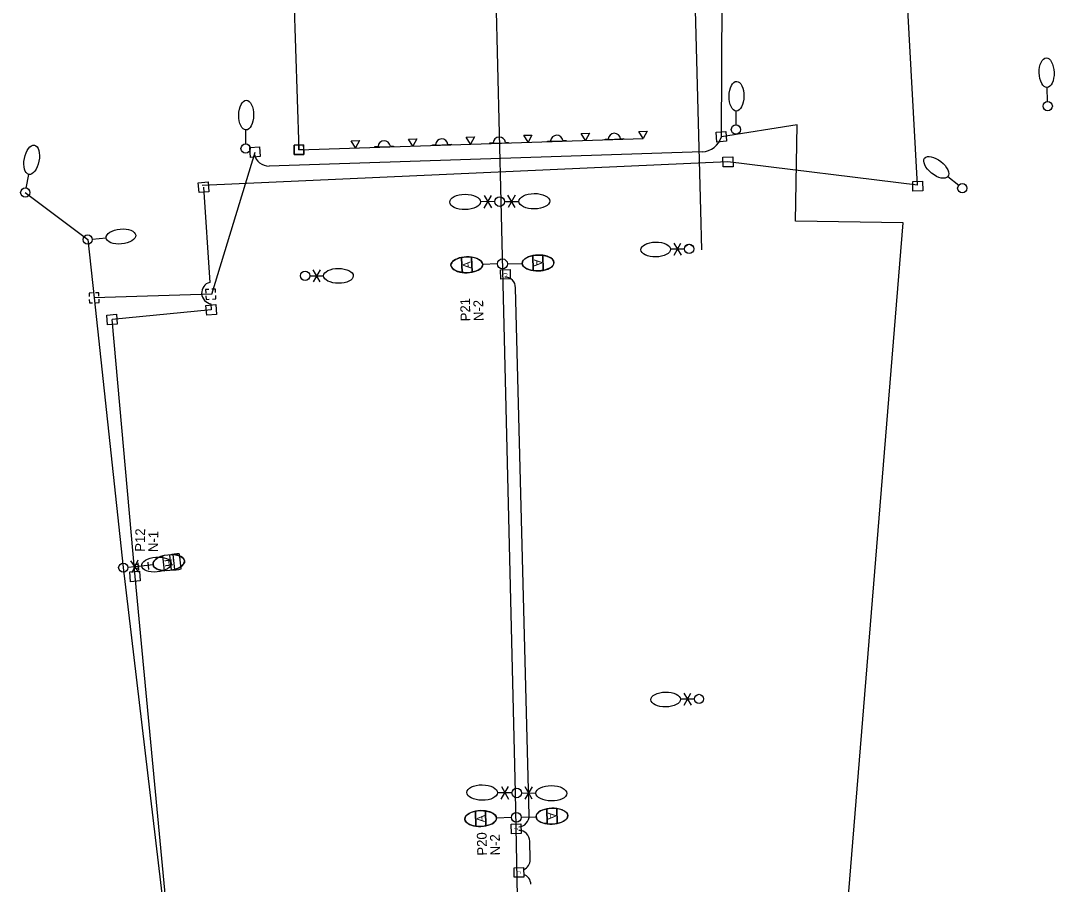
# Model space of a CAD drawing. Extents: x 925407 to 930994, y 604905 to 637063.
# Drawn here: x 929578 to 930105, y 610061 to 610502 of the extents above; entities that cross this region are included whole.
import ezdxf

# ---------------------------------------------------------------- set-up
doc = ezdxf.new("R2010")
doc.units = 0
for name, color, linetype in [('ActivePointCell_dp', 7, 'Continuous'), ('Conduit', 7, 'Continuous'), ('ConduitDB', 7, 'Continuous'), ('ConduitJB', 7, 'Continuous'), ('ConduitOT', 7, 'Continuous'), ('GPKDrCellIns_dp', 7, 'Continuous'), ('LightingMisc', 7, 'Continuous'), ('LiteCond_ep', 7, 'Continuous'), ('Miscellaneous2', 7, 'Continuous'), ('Miscellaneous9', 7, 'Continuous'), ('PoleLight', 7, 'Continuous'), ('PoleLight_ep', 7, 'Continuous'), ('PullBox', 7, 'Continuous')]:
    doc.layers.add(name, color=color, linetype=linetype)

msp = doc.modelspace()

# ---------------------------------------------------------------- linework, layer by layer
at = {"layer": 'ActivePointCell_dp'}
for p, q in [((929638.26, 610221.47), (929637.95, 610225.23)), ((929643.24, 610221.88), (929642.93, 610225.65))]:
    msp.add_line(p, q, dxfattribs=at)
at = {"layer": 'Conduit'}
for p, q in [((929822.99, 610409.48), (929815.93, 610700.2)), ((929935.24, 610442.43), (929936.2, 610609.56)), ((929973.9, 610448.58), (929935.24, 610442.43)), ((929973.1, 610399.48), (929973.9, 610448.58)), ((929675.41, 610362.13), (929697.45, 610434.6)), ((929580.32, 610414), (929612.12, 610390.03)), ((930027.95, 610398.52), (929973.1, 610399.48)), ((929999.47, 610048.38), (930027.95, 610398.52)), ((929612.12, 610390.03), (929615.35, 610360.32)), ((929675.41, 610362.13), (929615.35, 610360.32))]:
    msp.add_line(p, q, dxfattribs=at)
at = {"layer": 'ConduitDB'}
for p, q in [((930035.34, 610417.86), (930021.51, 610662.68)), ((930035.34, 610417.86), (929938.62, 610429.6)), ((929675.11, 610354.21), (929624.53, 610349.24))]:
    msp.add_line(p, q, dxfattribs=at)
at = {"layer": 'ConduitJB'}
for p, q in [((929717.31, 610513.51), (929719.84, 610435.81)), ((929719.84, 610435.81), (929895.35, 610441.53))]:
    msp.add_line(p, q, dxfattribs=at)
at = {"layer": 'ConduitOT'}
for p, q in [((929925.42, 610434.75), (929704.65, 610427.52)), ((929938.62, 610429.6), (929670.54, 610417.62)), ((929671.18, 610416.73), (929674.35, 610368.23)), ((929837.24, 610096.42), (929830.3, 610365.46)), ((929674.92, 610357.28), (929675.11, 610354.21)), ((929636.27, 610218.27), (929624.53, 610349.24)), ((929653.36, 610037.56), (929636.27, 610218.27)), ((929837.8, 610074), (929837.57, 610083.29))]:
    msp.add_line(p, q, dxfattribs=at)
for centre, radius, start, end in [((929925.07, 610445.32), 10.57, 271.8776, 344.1499), ((929704.41, 610434.96), 7.45, 191.5541, 271.8776), ((929675.85, 610362.82), 5.62, 105.4594, 261.004), ((929824.79, 610365.45), 5.5, 0.1119, 90.2648), ((929831.74, 610096.17), 5.5, 272.4059, 2.5588), ((929832.06, 610083.28), 5.5, 0.1119, 90.2648), ((929832.31, 610073.86), 5.5, 292.6823, 1.4756), ((929832.63, 610061.18), 5.5, 1.4756, 70.3354)]:
    msp.add_arc(centre, radius, start, end, dxfattribs=at)
at = {"layer": 'GPKDrCellIns_dp'}
for p, q in [((929924.78, 610404.78), (929918.49, 610648.7)), ((929924.78, 610404.78), (929918.49, 610648.7)), ((929925.29, 610384.79), (929924.78, 610404.78)), ((929925.29, 610384.79), (929924.78, 610404.78))]:
    msp.add_line(p, q, dxfattribs=at)
at = {"layer": 'LightingMisc'}
for p, q in [((929875.92, 610441.24), (929877.52, 610441.28)), ((929875.93, 610440.92), (929875.92, 610441.24)), ((929885.44, 610441.18), (929875.93, 610440.92)), ((929883.83, 610441.45), (929885.43, 610441.49)), ((929885.43, 610441.49), (929885.44, 610441.18)), ((929758.56, 610437.42), (929760.17, 610437.46)), ((929758.57, 610437.1), (929758.56, 610437.42)), ((929768.09, 610437.36), (929758.57, 610437.1)), ((929766.48, 610437.63), (929768.08, 610437.68)), ((929768.08, 610437.68), (929768.09, 610437.36)), ((929787.9, 610438.37), (929789.5, 610438.42)), ((929787.91, 610438.06), (929787.9, 610438.37)), ((929797.43, 610438.31), (929787.91, 610438.06)), ((929795.82, 610438.59), (929797.42, 610438.63)), ((929797.42, 610438.63), (929797.43, 610438.31)), ((929817.24, 610439.33), (929818.84, 610439.37)), ((929817.25, 610439.01), (929817.24, 610439.33)), ((929826.77, 610439.27), (929817.25, 610439.01)), ((929825.15, 610439.54), (929826.76, 610439.58)), ((929826.76, 610439.58), (929826.77, 610439.27)), ((929846.58, 610440.28), (929848.18, 610440.33)), ((929846.59, 610439.97), (929846.58, 610440.28)), ((929856.1, 610440.22), (929846.59, 610439.97)), ((929854.49, 610440.5), (929856.09, 610440.54)), ((929856.09, 610440.54), (929856.1, 610440.22))]:
    msp.add_line(p, q, dxfattribs=at)
for points in [[(929775.77, 610441.29), (929779.99, 610441.43), (929778, 610437.71)], [(929805.11, 610442.25), (929809.33, 610442.39), (929807.34, 610438.67)], [(929834.45, 610443.2), (929838.67, 610443.34), (929836.68, 610439.62)], [(929863.79, 610444.16), (929868, 610444.3), (929866.02, 610440.58)], [(929893.13, 610445.11), (929897.34, 610445.25), (929895.35, 610441.53)], [(929746.43, 610440.34), (929750.65, 610440.48), (929748.66, 610436.76)]]:
    msp.add_lwpolyline(points, close=True, dxfattribs=at)
for centre in [(929792.67, 610438.19), (929822.01, 610439.14), (929851.35, 610440.09), (929880.68, 610441.05), (929763.33, 610437.23)]:
    msp.add_arc(centre, 3.17, 7.2789, 175.8005, dxfattribs=at)
at = {"layer": 'LiteCond_ep'}
for p, q in [((929719.76, 610438.24), (929717.35, 610438.17)), ((929717.35, 610438.17), (929717.48, 610433.33)), ((929722.2, 610438.3), (929719.76, 610438.24)), ((929719.84, 610435.81), (929719.76, 610438.24)), ((929719.76, 610438.24), (929719.84, 610435.81)), ((929722.26, 610435.89), (929719.84, 610435.81)), ((929719.84, 610435.81), (929722.26, 610435.89)), ((929722.26, 610435.89), (929722.2, 610438.3)), ((929722.32, 610433.46), (929722.26, 610435.89)), ((929717.48, 610433.33), (929722.32, 610433.46)), ((929615.35, 610360.32), (929630.28, 610222.78)), ((929630.28, 610222.78), (929651.34, 610044.22))]:
    msp.add_line(p, q, dxfattribs=at)
msp.add_lwpolyline([(929761.96, 608002.93), (929764.99, 608303.01), (929781.87, 608603.48), (929797.97, 608896.18), (929815.17, 609205.52), (929830.71, 609505.82), (929836.14, 609806.66), (929830.32, 610108.12), (929822.99, 610409.48)], dxfattribs=at)
at = {"layer": 'Miscellaneous2'}
for p, q in [((929802.81, 610380.95), (929802.81, 610380.95)), ((929802.81, 610380.95), (929803.01, 610373.29)), ((929808.11, 610373.42), (929807.91, 610381.08)), ((929807.91, 610381.08), (929807.91, 610381.08)), ((929839.15, 610381.89), (929839.15, 610381.89)), ((929839.15, 610381.89), (929839.35, 610374.22)), ((929844.45, 610374.35), (929844.25, 610382.02)), ((929844.25, 610382.02), (929844.25, 610382.02)), ((929653.79, 610229.21), (929654.7, 610221.6)), ((929659.76, 610222.2), (929658.86, 610229.82)), ((929654.7, 610221.6), (929654.7, 610221.6)), ((929659.76, 610222.2), (929659.76, 610222.2)), ((929809.84, 610098.58), (929809.84, 610098.58)), ((929809.84, 610098.58), (929810.11, 610090.92)), ((929815.2, 610091.1), (929814.94, 610098.76)), ((929814.94, 610098.76), (929814.94, 610098.76)), ((929846.18, 610099.82), (929846.18, 610099.82)), ((929846.18, 610099.82), (929846.44, 610092.16)), ((929851.53, 610092.33), (929851.27, 610099.99)), ((929851.27, 610099.99), (929851.27, 610099.99))]:
    msp.add_line(p, q, dxfattribs=at)
for centre, major_axis, start_param, end_param in [((929805.46, 610377.18), (8.08, 0.21), 1.249648, 1.891946), ((929841.8, 610378.12), (8.08, 0.21), 1.249648, 1.891946), ((929805.46, 610377.18), (8.08, 0.21), 4.391271, 5.033538), ((929805.46, 610377.18), (8.08, 0.21), 4.391241, 4.391271), ((929841.8, 610378.12), (8.08, 0.21), 4.391271, 5.033538), ((929841.8, 610378.12), (8.08, 0.21), 4.391241, 4.391271), ((929656.78, 610225.71), (-8.02, -0.96), 4.391271, 5.033538), ((929656.78, 610225.71), (-8.02, -0.96), 4.391241, 4.391271), ((929656.78, 610225.71), (-8.02, -0.96), 1.249648, 1.891946), ((929812.52, 610094.84), (8.07, 0.28), 1.249648, 1.891946), ((929848.86, 610096.08), (8.07, 0.28), 1.249648, 1.891946), ((929812.52, 610094.84), (8.07, 0.28), 4.391271, 5.033538), ((929812.52, 610094.84), (8.07, 0.28), 4.391241, 4.391271), ((929848.86, 610096.08), (8.07, 0.28), 4.391271, 5.033538), ((929848.86, 610096.08), (8.07, 0.28), 4.391241, 4.391271)]:
    msp.add_ellipse(centre, major_axis=major_axis, ratio=0.5, start_param=start_param, end_param=end_param, dxfattribs=at)
at = {"layer": 'PoleLight'}
for p, q in [((929803.01, 610373.29), (929802.81, 610380.95)), ((929807.91, 610381.08), (929808.11, 610373.42)), ((929826.15, 610377.72), (929833.72, 610377.91)), ((929839.35, 610374.22), (929839.15, 610381.89)), ((929844.25, 610382.02), (929844.45, 610374.35)), ((929821.1, 610377.59), (929813.53, 610377.39)), ((929651.38, 610221.22), (929650.47, 610228.83)), ((929655.54, 610229.44), (929656.44, 610221.83)), ((929637.92, 610223.48), (929645.44, 610224.38)), ((929810.11, 610090.92), (929809.84, 610098.58)), ((929814.94, 610098.76), (929815.2, 610091.1)), ((929846.44, 610092.16), (929846.18, 610099.82)), ((929851.27, 610099.99), (929851.53, 610092.33)), ((929828.17, 610095.37), (929820.6, 610095.11)), ((929833.21, 610095.54), (929840.78, 610095.8))]:
    msp.add_line(p, q, dxfattribs=at)
for centre, radius in [((929823.63, 610377.65), 2.52), ((929823.63, 610377.65), 2.52), ((929636.96, 610223.35), 1.14), ((929830.69, 610095.46), 2.52), ((929830.69, 610095.46), 2.52)]:
    msp.add_circle(centre, radius, dxfattribs=at)
for centre, major_axis in [((929805.46, 610377.18), (8.08, 0.21)), ((929841.8, 610378.12), (8.08, 0.21)), ((929653.46, 610225.33), (-8.02, -0.96)), ((929812.52, 610094.84), (8.07, 0.28)), ((929848.86, 610096.08), (8.07, 0.28))]:
    msp.add_ellipse(centre, major_axis=major_axis, ratio=0.5, dxfattribs=at)
for centre, major_axis, start_param, end_param in [((929805.46, 610377.18), (8.08, 0.21), 1.891945, 4.391241), ((929805.46, 610377.18), (8.08, 0.21), 0.847605, 1.249648), ((929805.46, 610377.18), (8.08, 0.21), 0, 0.847605), ((929841.8, 610378.12), (8.08, 0.21), 1.891945, 4.391241), ((929841.8, 610378.12), (8.08, 0.21), 0.847605, 1.249648), ((929841.8, 610378.12), (8.08, 0.21), 5.033538, 6.283185), ((929841.8, 610378.12), (8.08, 0.21), 0, 0.847605), ((929805.46, 610377.18), (8.08, 0.21), 5.033538, 6.283185), ((929653.46, 610225.33), (-8.02, -0.96), 5.033538, 6.283185), ((929653.46, 610225.33), (-8.02, -0.96), 1.891945, 4.391241), ((929653.46, 610225.33), (-8.02, -0.96), 0, 0.847605), ((929653.46, 610225.33), (-8.02, -0.96), 0.847605, 1.249648), ((929812.52, 610094.84), (8.07, 0.28), 1.891945, 4.391241), ((929812.52, 610094.84), (8.07, 0.28), 0.847605, 1.249648), ((929848.86, 610096.08), (8.07, 0.28), 1.891945, 4.391241), ((929848.86, 610096.08), (8.07, 0.28), 0.847605, 1.249648), ((929848.86, 610096.08), (8.07, 0.28), 0, 0.847605), ((929812.52, 610094.84), (8.07, 0.28), 5.033538, 6.283185), ((929812.52, 610094.84), (8.07, 0.28), 0, 0.847605), ((929848.86, 610096.08), (8.07, 0.28), 5.033538, 6.283185)]:
    msp.add_ellipse(centre, major_axis=major_axis, ratio=0.5, start_param=start_param, end_param=end_param, dxfattribs=at)
at = {"layer": 'PoleLight_ep'}
for p, q in [((930101.57, 610460.47), (930101.36, 610467.57)), ((929942.73, 610448.46), (929942.85, 610455.56)), ((929692.7, 610438.81), (929692.82, 610445.91)), ((929580.77, 610416.32), (929582.12, 610423.29)), ((930056.26, 610417.68), (930050.72, 610422.11)), ((929814.31, 610412.46), (929818.05, 610406.14)), ((929814.38, 610406.1), (929817.99, 610412.5)), ((929824.68, 610409.43), (929832.03, 610409.51)), ((929830.15, 610406.35), (929826.41, 610412.67)), ((929830.09, 610412.71), (929826.48, 610406.31)), ((929819.78, 610409.38), (929812.43, 610409.3)), ((929614.48, 610390.25), (929621.54, 610390.9)), ((929916.45, 610385.23), (929909.35, 610385.12)), ((929916.45, 610385.22), (929909.36, 610385.11)), ((929911.08, 610388.21), (929914.73, 610382.12)), ((929911.18, 610382.06), (929914.63, 610388.26)), ((929730.67, 610374.63), (929727.11, 610368.49)), ((929730.66, 610368.49), (929727.12, 610374.64)), ((929725.34, 610371.57), (929732.44, 610371.56)), ((929638.2, 610220.43), (929634.11, 610226.21)), ((929637.63, 610226.54), (929634.67, 610220.11)), ((929632.63, 610223), (929639.68, 610223.65)), ((929916.13, 610158.78), (929919.78, 610152.69)), ((929916.23, 610152.64), (929919.67, 610158.84)), ((929921.5, 610155.79), (929914.41, 610155.68)), ((929823, 610104.78), (929826.74, 610111.11)), ((929823.07, 610111.15), (929826.68, 610104.74)), ((929838.85, 610111.06), (929835.1, 610104.73)), ((929838.78, 610104.69), (929835.17, 610111.1)), ((929828.47, 610107.95), (929821.12, 610108.02)), ((929833.37, 610107.89), (929840.72, 610107.82))]:
    msp.add_line(p, q, dxfattribs=at)
for centre, radius in [((930101.65, 610458.11), 2.37), ((929942.69, 610446.1), 2.37), ((929692.67, 610436.45), 2.37), ((929580.32, 610414), 2.37), ((930058.11, 610416.2), 2.37), ((929822.23, 610409.41), 2.45), ((929612.12, 610390.03), 2.37), ((929918.82, 610385.26), 2.37), ((929918.82, 610385.26), 2.36), ((929722.98, 610371.57), 2.36), ((929630.28, 610222.78), 2.36), ((929923.86, 610155.83), 2.36), ((929830.92, 610107.92), 2.45)]:
    msp.add_circle(centre, radius, dxfattribs=at)
for centre, major_axis in [((930101.12, 610475.13), (-0.23, 7.57)), ((929942.97, 610463.13), (0.12, 7.57)), ((929692.94, 610453.48), (0.12, 7.57)), ((929583.56, 610430.72), (1.44, 7.43)), ((930044.81, 610426.84), (-5.91, 4.73)), ((929804.59, 610409.22), (-7.84, -0.08)), ((929839.87, 610409.59), (7.84, 0.08)), ((929629.08, 610391.6), (7.54, 0.69)), ((929901.78, 610385), (-7.57, -0.12)), ((929901.79, 610384.98), (-7.57, -0.13)), ((929740, 610371.55), (7.57, -0.01)), ((929647.19, 610224.34), (7.52, 0.69)), ((929906.84, 610155.55), (-7.57, -0.13)), ((929813.28, 610108.11), (-7.84, 0.08)), ((929848.56, 610107.73), (7.84, -0.08))]:
    msp.add_ellipse(centre, major_axis=major_axis, ratio=0.5, dxfattribs=at)
at = {"layer": 'PullBox'}
for p, q in [((929932.55, 610444.73), (929937.54, 610445.12)), ((929932.95, 610439.74), (929932.55, 610444.73)), ((929937.54, 610445.12), (929937.93, 610440.14)), ((929694.76, 610436.9), (929699.74, 610437.29)), ((929695.15, 610431.92), (929694.76, 610436.9)), ((929699.74, 610437.29), (929700.14, 610432.31)), ((929717.35, 610438.17), (929722.2, 610438.3)), ((929717.48, 610433.33), (929717.35, 610438.17)), ((929722.2, 610438.3), (929722.32, 610433.46)), ((929937.93, 610440.14), (929932.95, 610439.74)), ((929700.14, 610432.31), (929695.15, 610431.92)), ((929722.32, 610433.46), (929717.48, 610433.33)), ((929936.06, 610432.04), (929941.06, 610432.17)), ((929936.19, 610427.04), (929936.06, 610432.04)), ((929941.06, 610432.17), (929941.19, 610427.17)), ((929941.19, 610427.17), (929936.19, 610427.04)), ((929668.49, 610419.02), (929673.48, 610419.42)), ((929668.89, 610414.04), (929668.49, 610419.02)), ((929673.48, 610419.42), (929673.87, 610414.43)), ((930032.81, 610419.72), (930037.81, 610419.85)), ((930032.94, 610414.72), (930032.81, 610419.72)), ((930037.93, 610414.85), (930032.94, 610414.72)), ((930037.81, 610419.85), (930037.93, 610414.85)), ((929673.87, 610414.43), (929668.89, 610414.04)), ((929822.66, 610374.66), (929827.51, 610374.78)), ((929822.79, 610369.81), (929822.66, 610374.66)), ((929827.51, 610374.78), (929827.63, 610369.94)), ((929827.63, 610369.94), (929822.79, 610369.81)), ((929672.42, 610356.51), (929677.41, 610356.9)), ((929677.41, 610356.9), (929677.8, 610351.92)), ((929621.84, 610351.54), (929626.82, 610351.93)), ((929622.23, 610346.55), (929621.84, 610351.54)), ((929626.82, 610351.93), (929627.22, 610346.95)), ((929672.82, 610351.52), (929672.42, 610356.51)), ((929677.8, 610351.92), (929672.82, 610351.52)), ((929627.22, 610346.95), (929622.23, 610346.55)), ((929633.58, 610220.56), (929638.57, 610220.96)), ((929633.98, 610215.58), (929633.58, 610220.56)), ((929638.57, 610220.96), (929638.96, 610215.97)), ((929638.96, 610215.97), (929633.98, 610215.58)), ((929828.14, 610091.97), (929832.99, 610092.08)), ((929828.26, 610087.13), (929828.14, 610091.97)), ((929832.99, 610092.08), (929833.1, 610087.24)), ((929833.1, 610087.24), (929828.26, 610087.13)), ((929829.56, 610069.72), (929834.4, 610069.84)), ((929829.67, 610064.88), (929829.56, 610069.72)), ((929834.4, 610069.84), (929834.52, 610064.99)), ((929834.52, 610064.99), (929829.67, 610064.88))]:
    msp.add_line(p, q, dxfattribs=at)
for points in [[(929614.5, 610362.8), (929612.82, 610362.75), (929612.88, 610360.99)], [(929617.87, 610361.14), (929617.82, 610362.9), (929616.05, 610362.85)], [(929673.92, 610364.63), (929672.24, 610364.55), (929672.33, 610362.79)], [(929677.32, 610363.03), (929677.24, 610364.79), (929675.47, 610364.7)], [(929612.92, 610359.49), (929612.97, 610357.75), (929614.65, 610357.81)], [(929616.2, 610357.85), (929617.97, 610357.91)], [(929617.97, 610357.91), (929617.92, 610359.64)], [(929672.4, 610361.3), (929672.48, 610359.56), (929674.15, 610359.64)], [(929675.7, 610359.71), (929677.47, 610359.8)], [(929677.47, 610359.8), (929677.39, 610361.53)]]:
    msp.add_lwpolyline(points, dxfattribs=at)

# ---------------------------------------------------------------- texts
at = {"layer": 'ActivePointCell_dp'}
for s, rotation, p in [('P21', 91.1767, (929807.29, 610348.41)), ('N-2', 91.1767, (929813.99, 610348.54)), ('P12', 89.0297, (929641.26, 610230.82)), ('N-1', 89.0297, (929647.96, 610230.7)), ('P20', 91.1767, (929815.77, 610076.01)), ('N-2', 91.1767, (929822.47, 610076.15))]:
    msp.add_text(s, height=5, rotation=rotation, dxfattribs=at).set_placement(p)
at = {"layer": 'Miscellaneous9'}
for s, rotation, p in [('A', 91.4757, (929807.55, 610375.34)), ('A', 271.4757, (929839.71, 610379.97)), ('H', 276.7896, (929651.21, 610226.94)), ('A', 91.9513, (929814.63, 610093.01)), ('A', 271.9513, (929846.75, 610097.91))]:
    msp.add_text(s, height=4.08, rotation=rotation, dxfattribs=at).set_placement(p)
at = {"layer": 'PullBox'}
for rotation, p in [(91.4756, (929826.13, 610371.66)), (91.3353, (929831.61, 610088.97)), (91.3353, (929833.02, 610066.72))]:
    msp.add_text('J', height=1.94, rotation=rotation, dxfattribs=at).set_placement(p)

doc.saveas('drawing.dxf')
